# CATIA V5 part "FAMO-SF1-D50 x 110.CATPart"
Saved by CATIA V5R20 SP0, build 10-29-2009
Part number: FAMO-SF1-D50 x 110
Definition: NONE
Nomenclature: FAMO-SF1-D50 x 110
Source: Unknown
Description: FAMO-SF1-D50 x 110
Bounding box of the stored display mesh (mm): x -53 to 57, y -39.5 to 39.5, z -39.5 to 39.5
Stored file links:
  C:\Users\Utente\Desktop\IO LAVORO\3D X SITO CF\X SITO\FAMO\FAMO-SF1-D50 x 110.CATPart
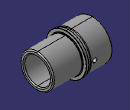
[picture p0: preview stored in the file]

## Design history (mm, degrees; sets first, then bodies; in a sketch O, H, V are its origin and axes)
Body1 "FAMO-SF1-D50 x 110" (main body)
  Solid1: solid without history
